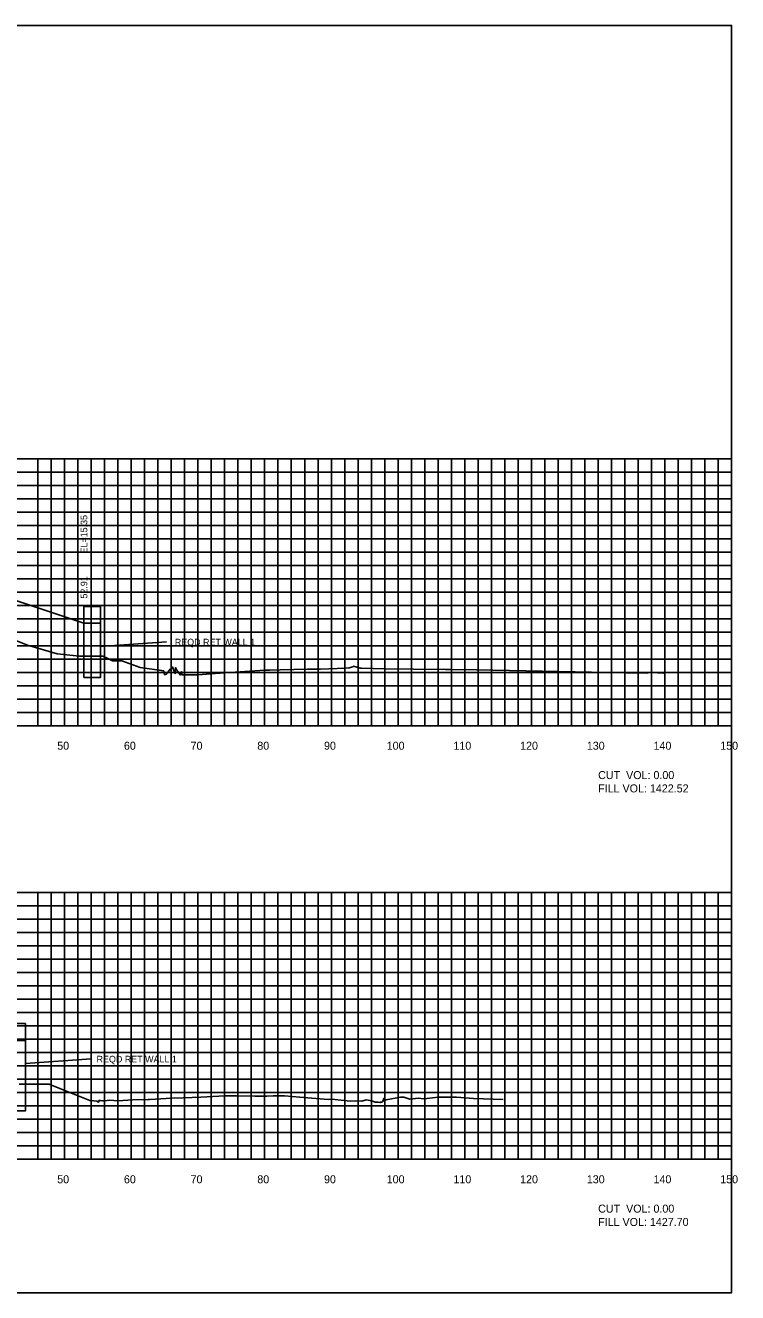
# Model space of a CAD drawing. Extents: x 1797652 to 1804145, y 245981 to 250269.
# Drawn here: x 1803355.1 to 1803461.9, y 250079.4 to 250269.4 of the extents above; entities that cross this region are included whole.
import ezdxf

# ---------------------------------------------------------------- set-up
doc = ezdxf.new("R2010")
doc.units = 0
for name, color, linetype in [('10', 7, 'Continuous'), ('3', 7, 'Continuous'), ('60', 7, 'Continuous'), ('ANNO-TXT', 7, 'Continuous'), ('CL-CNST', 7, 'Continuous'), ('Level 62', 7, 'Continuous'), ('M-ROADS', 7, 'Continuous')]:
    doc.layers.add(name, color=color, linetype=linetype)

msp = doc.modelspace()

# ---------------------------------------------------------------- linework, layer by layer
msp.add_line((1803363.91, 250179.78), (1803363.91, 250181.78))
msp.add_lwpolyline([(1803161, 250079.43), (1803461, 250079.43), (1803461, 250269.43), (1803161, 250269.43)], close=True)
at = {"layer": '3'}
for p, q in [((1803376.3, 250177.02), (1803366.41, 250176.31)), ((1803365.01, 250114.49), (1803355.12, 250113.78))]:
    msp.add_line(p, q, dxfattribs=at)
at = {"layer": '60'}
for p, q in [((1803461, 250164.43), (1803461, 250204.43)), ((1803461.06, 250204.43), (1803461, 250204.43)), ((1803461.06, 250194.43), (1803461, 250194.43)), ((1803461.06, 250184.43), (1803461, 250184.43)), ((1803461.06, 250174.43), (1803461, 250174.43)), ((1803161, 250164.43), (1803461, 250164.43)), ((1803361, 250164.37), (1803361, 250164.43)), ((1803371, 250164.37), (1803371, 250164.43)), ((1803381, 250164.37), (1803381, 250164.43)), ((1803391, 250164.37), (1803391, 250164.43)), ((1803401, 250164.37), (1803401, 250164.43)), ((1803411, 250164.37), (1803411, 250164.43)), ((1803421, 250164.37), (1803421, 250164.43)), ((1803431, 250164.37), (1803431, 250164.43)), ((1803441, 250164.37), (1803441, 250164.43)), ((1803451, 250164.37), (1803451, 250164.43)), ((1803461, 250164.37), (1803461, 250164.43)), ((1803461.06, 250164.43), (1803461, 250164.43)), ((1803461, 250099.43), (1803461, 250139.43)), ((1803461.06, 250139.43), (1803461, 250139.43)), ((1803461.06, 250129.43), (1803461, 250129.43)), ((1803461.06, 250119.43), (1803461, 250119.43)), ((1803461.06, 250109.43), (1803461, 250109.43)), ((1803161, 250099.43), (1803461, 250099.43)), ((1803361, 250099.37), (1803361, 250099.43)), ((1803371, 250099.37), (1803371, 250099.43)), ((1803381, 250099.37), (1803381, 250099.43)), ((1803391, 250099.37), (1803391, 250099.43)), ((1803401, 250099.37), (1803401, 250099.43)), ((1803411, 250099.37), (1803411, 250099.43)), ((1803421, 250099.37), (1803421, 250099.43)), ((1803431, 250099.37), (1803431, 250099.43)), ((1803441, 250099.37), (1803441, 250099.43)), ((1803451, 250099.37), (1803451, 250099.43)), ((1803461, 250099.37), (1803461, 250099.43)), ((1803461.06, 250099.43), (1803461, 250099.43))]:
    msp.add_line(p, q, dxfattribs=at)
at = {"layer": 'CL-CNST'}
msp.add_lwpolyline([(1803284.69, 250193.39), (1803286.5, 250193.32), (1803286.83, 250193.32), (1803287, 250192.82), (1803289, 250192.98), (1803295, 250193.11), (1803311, 250193.46), (1803319, 250193.14), (1803324.5, 250192.92), (1803363.91, 250179.78)], dxfattribs=at)
for points in [[(1803366.41, 250179.78), (1803363.91, 250179.78), (1803363.91, 250182.28), (1803366.41, 250182.28)], [(1803363.91, 250171.68), (1803366.41, 250171.68), (1803366.41, 250179.78), (1803363.91, 250179.78)], [(1803355.12, 250117.26), (1803352.62, 250117.26), (1803352.62, 250119.76), (1803355.12, 250119.76)], [(1803352.62, 250106.68), (1803355.12, 250106.68), (1803355.12, 250117.26), (1803352.62, 250117.26)]]:
    msp.add_lwpolyline(points, close=True, dxfattribs=at)
at = {"layer": 'Level 62'}
for p, q in [((1803161, 250204.43), (1803461, 250204.43)), ((1803357, 250164.43), (1803357, 250204.43)), ((1803359, 250164.43), (1803359, 250204.43)), ((1803361, 250164.43), (1803361, 250204.43)), ((1803363, 250164.43), (1803363, 250204.43)), ((1803365, 250164.43), (1803365, 250204.43)), ((1803367, 250164.43), (1803367, 250204.43)), ((1803369, 250164.43), (1803369, 250204.43)), ((1803371, 250164.43), (1803371, 250204.43)), ((1803373, 250164.43), (1803373, 250204.43)), ((1803375, 250164.43), (1803375, 250204.43)), ((1803377, 250164.43), (1803377, 250204.43)), ((1803379, 250164.43), (1803379, 250204.43)), ((1803381, 250164.43), (1803381, 250204.43)), ((1803383, 250164.43), (1803383, 250204.43)), ((1803385, 250164.43), (1803385, 250204.43)), ((1803387, 250164.43), (1803387, 250204.43)), ((1803389, 250164.43), (1803389, 250204.43)), ((1803391, 250164.43), (1803391, 250204.43)), ((1803393, 250164.43), (1803393, 250204.43)), ((1803395, 250164.43), (1803395, 250204.43)), ((1803397, 250164.43), (1803397, 250204.43)), ((1803399, 250164.43), (1803399, 250204.43)), ((1803401, 250164.43), (1803401, 250204.43)), ((1803403, 250164.43), (1803403, 250204.43)), ((1803405, 250164.43), (1803405, 250204.43)), ((1803407, 250164.43), (1803407, 250204.43)), ((1803409, 250164.43), (1803409, 250204.43)), ((1803411, 250164.43), (1803411, 250204.43)), ((1803413, 250164.43), (1803413, 250204.43)), ((1803415, 250164.43), (1803415, 250204.43)), ((1803417, 250164.43), (1803417, 250204.43)), ((1803419, 250164.43), (1803419, 250204.43)), ((1803421, 250164.43), (1803421, 250204.43)), ((1803423, 250164.43), (1803423, 250204.43)), ((1803425, 250164.43), (1803425, 250204.43)), ((1803427, 250164.43), (1803427, 250204.43)), ((1803429, 250164.43), (1803429, 250204.43)), ((1803431, 250164.43), (1803431, 250204.43)), ((1803433, 250164.43), (1803433, 250204.43)), ((1803435, 250164.43), (1803435, 250204.43)), ((1803437, 250164.43), (1803437, 250204.43)), ((1803439, 250164.43), (1803439, 250204.43)), ((1803441, 250164.43), (1803441, 250204.43)), ((1803443, 250164.43), (1803443, 250204.43)), ((1803445, 250164.43), (1803445, 250204.43)), ((1803447, 250164.43), (1803447, 250204.43)), ((1803449, 250164.43), (1803449, 250204.43)), ((1803451, 250164.43), (1803451, 250204.43)), ((1803453, 250164.43), (1803453, 250204.43)), ((1803455, 250164.43), (1803455, 250204.43)), ((1803457, 250164.43), (1803457, 250204.43)), ((1803459, 250164.43), (1803459, 250204.43)), ((1803461, 250164.43), (1803461, 250204.43)), ((1803161, 250202.43), (1803461, 250202.43)), ((1803161, 250200.43), (1803461, 250200.43)), ((1803161, 250198.43), (1803461, 250198.43)), ((1803161, 250196.43), (1803461, 250196.43)), ((1803161, 250194.43), (1803461, 250194.43)), ((1803161, 250192.43), (1803461, 250192.43)), ((1803161, 250190.43), (1803461, 250190.43)), ((1803161, 250188.43), (1803461, 250188.43)), ((1803161, 250186.43), (1803461, 250186.43)), ((1803161, 250184.43), (1803461, 250184.43)), ((1803161, 250182.43), (1803461, 250182.43)), ((1803161, 250180.43), (1803461, 250180.43)), ((1803161, 250178.43), (1803461, 250178.43)), ((1803161, 250176.43), (1803461, 250176.43)), ((1803161, 250174.43), (1803461, 250174.43)), ((1803161, 250172.43), (1803461, 250172.43)), ((1803161, 250170.43), (1803461, 250170.43)), ((1803161, 250168.43), (1803461, 250168.43)), ((1803161, 250166.43), (1803461, 250166.43)), ((1803161, 250164.43), (1803461, 250164.43)), ((1803161, 250139.43), (1803461, 250139.43)), ((1803357, 250099.43), (1803357, 250139.43)), ((1803359, 250099.43), (1803359, 250139.43)), ((1803361, 250099.43), (1803361, 250139.43)), ((1803363, 250099.43), (1803363, 250139.43)), ((1803365, 250099.43), (1803365, 250139.43)), ((1803367, 250099.43), (1803367, 250139.43)), ((1803369, 250099.43), (1803369, 250139.43)), ((1803371, 250099.43), (1803371, 250139.43)), ((1803373, 250099.43), (1803373, 250139.43)), ((1803375, 250099.43), (1803375, 250139.43)), ((1803377, 250099.43), (1803377, 250139.43)), ((1803379, 250099.43), (1803379, 250139.43)), ((1803381, 250099.43), (1803381, 250139.43)), ((1803383, 250099.43), (1803383, 250139.43)), ((1803385, 250099.43), (1803385, 250139.43)), ((1803387, 250099.43), (1803387, 250139.43)), ((1803389, 250099.43), (1803389, 250139.43)), ((1803391, 250099.43), (1803391, 250139.43)), ((1803393, 250099.43), (1803393, 250139.43)), ((1803395, 250099.43), (1803395, 250139.43)), ((1803397, 250099.43), (1803397, 250139.43)), ((1803399, 250099.43), (1803399, 250139.43)), ((1803401, 250099.43), (1803401, 250139.43)), ((1803403, 250099.43), (1803403, 250139.43)), ((1803405, 250099.43), (1803405, 250139.43)), ((1803407, 250099.43), (1803407, 250139.43)), ((1803409, 250099.43), (1803409, 250139.43)), ((1803411, 250099.43), (1803411, 250139.43)), ((1803413, 250099.43), (1803413, 250139.43)), ((1803415, 250099.43), (1803415, 250139.43)), ((1803417, 250099.43), (1803417, 250139.43)), ((1803419, 250099.43), (1803419, 250139.43)), ((1803421, 250099.43), (1803421, 250139.43)), ((1803423, 250099.43), (1803423, 250139.43)), ((1803425, 250099.43), (1803425, 250139.43)), ((1803427, 250099.43), (1803427, 250139.43)), ((1803429, 250099.43), (1803429, 250139.43)), ((1803431, 250099.43), (1803431, 250139.43)), ((1803433, 250099.43), (1803433, 250139.43)), ((1803435, 250099.43), (1803435, 250139.43)), ((1803437, 250099.43), (1803437, 250139.43)), ((1803439, 250099.43), (1803439, 250139.43)), ((1803441, 250099.43), (1803441, 250139.43)), ((1803443, 250099.43), (1803443, 250139.43)), ((1803445, 250099.43), (1803445, 250139.43)), ((1803447, 250099.43), (1803447, 250139.43)), ((1803449, 250099.43), (1803449, 250139.43)), ((1803451, 250099.43), (1803451, 250139.43)), ((1803453, 250099.43), (1803453, 250139.43)), ((1803455, 250099.43), (1803455, 250139.43)), ((1803457, 250099.43), (1803457, 250139.43)), ((1803459, 250099.43), (1803459, 250139.43)), ((1803461, 250099.43), (1803461, 250139.43)), ((1803161, 250137.43), (1803461, 250137.43)), ((1803161, 250135.43), (1803461, 250135.43)), ((1803161, 250133.43), (1803461, 250133.43)), ((1803161, 250131.43), (1803461, 250131.43)), ((1803161, 250129.43), (1803461, 250129.43)), ((1803161, 250127.43), (1803461, 250127.43)), ((1803161, 250125.43), (1803461, 250125.43)), ((1803161, 250123.43), (1803461, 250123.43)), ((1803161, 250121.43), (1803461, 250121.43)), ((1803161, 250119.43), (1803461, 250119.43)), ((1803161, 250117.43), (1803461, 250117.43)), ((1803161, 250115.43), (1803461, 250115.43)), ((1803161, 250113.43), (1803461, 250113.43)), ((1803161, 250111.43), (1803461, 250111.43)), ((1803161, 250109.43), (1803461, 250109.43)), ((1803161, 250107.43), (1803461, 250107.43)), ((1803161, 250105.43), (1803461, 250105.43)), ((1803161, 250103.43), (1803461, 250103.43)), ((1803161, 250101.43), (1803461, 250101.43)), ((1803161, 250099.43), (1803461, 250099.43))]:
    msp.add_line(p, q, dxfattribs=at)
at = {"layer": 'M-ROADS'}
for points in [[(1803352.2, 250177.82), (1803355.44, 250176.49), (1803359.88, 250175.2), (1803363.23, 250174.87), (1803363.32, 250174.87), (1803363.41, 250174.87), (1803366.73, 250174.88), (1803367.5, 250174.49), (1803368.21, 250174.17), (1803369.61, 250174.15), (1803372.35, 250173.16), (1803375.86, 250172.65), (1803376, 250172.06), (1803376.25, 250172.14), (1803376.89, 250172.95), (1803376.95, 250172.86), (1803377.12, 250173.23), (1803377.17, 250173.24), (1803377.24, 250173.13), (1803377.56, 250172.24), (1803377.56, 250172.23), (1803377.61, 250173.14), (1803377.7, 250173.03), (1803377.83, 250172.77), (1803378.21, 250172.21), (1803378.31, 250172.04), (1803378.39, 250172.09), (1803378.46, 250172.08), (1803378.53, 250172.54), (1803378.56, 250172.19), (1803378.65, 250172.05), (1803378.67, 250172.06), (1803379.13, 250172.06), (1803380.99, 250172.05), (1803383.58, 250172.26), (1803391.01, 250172.78), (1803391.77, 250172.78), (1803393.34, 250172.79), (1803397.4, 250172.91), (1803399.39, 250172.93), (1803403.1, 250173.08), (1803403.65, 250173.09), (1803404.24, 250173.24), (1803404.34, 250173.35), (1803404.69, 250173.27), (1803405.31, 250173.07), (1803405.36, 250173.06), (1803405.43, 250173.07), (1803405.52, 250173.08), (1803409.02, 250172.95), (1803417.6, 250172.88), (1803417.86, 250172.89), (1803418.11, 250172.88), (1803418.28, 250172.88), (1803418.32, 250172.87), (1803418.47, 250172.87), (1803418.85, 250172.85), (1803422.76, 250172.81), (1803444.96, 250172.36), (1803446.16, 250172.37), (1803448.41, 250172.33), (1803448.43, 250172.43), (1803448.71, 250172.42), (1803448.78, 250172.41), (1803448.91, 250172.39), (1803450.87, 250172.32), (1803450.93, 250172.28)], [(1803354.22, 250110.68), (1803355.94, 250110.68), (1803356.3, 250110.69), (1803358.56, 250110.69), (1803358.61, 250110.69), (1803358.67, 250110.69), (1803358.79, 250110.63), (1803364.77, 250108.24), (1803364.93, 250108.25), (1803365.83, 250108.16), (1803366.08, 250107.97), (1803366.13, 250108.08), (1803366.16, 250108.23), (1803366.4, 250108.22), (1803366.75, 250108.19), (1803366.83, 250108.19), (1803366.96, 250108.19), (1803367.03, 250108.19), (1803367.1, 250108.2), (1803367.7, 250108.3), (1803368.38, 250108.26), (1803369.01, 250108.21), (1803371.24, 250108.32), (1803373.55, 250108.39), (1803373.83, 250108.4), (1803377.05, 250108.61), (1803378.77, 250108.66), (1803381.42, 250108.74), (1803385.05, 250108.92), (1803386.79, 250108.92), (1803389.51, 250108.91), (1803391.32, 250108.91), (1803392.3, 250108.94), (1803393.62, 250108.92), (1803393.75, 250108.93), (1803393.8, 250108.95), (1803393.96, 250108.96), (1803396.25, 250108.75), (1803400.52, 250108.41), (1803401.07, 250108.42), (1803403.82, 250108.13), (1803404.6, 250108.18), (1803405.58, 250108.13), (1803406.23, 250108.32), (1803407.08, 250108.18), (1803407.57, 250108), (1803407.61, 250108), (1803407.95, 250108), (1803408, 250107.97), (1803408.26, 250107.96), (1803408.29, 250107.96), (1803408.34, 250107.93), (1803408.34, 250108), (1803408.61, 250108), (1803408.74, 250108.11), (1803408.85, 250108.56), (1803408.88, 250108.36), (1803408.94, 250108.33), (1803408.98, 250108.27), (1803409.03, 250108.34), (1803409.22, 250108.36), (1803411.38, 250108.75), (1803411.42, 250108.75), (1803411.43, 250108.75), (1803411.89, 250108.72), (1803412.79, 250108.42), (1803414.08, 250108.57), (1803414.8, 250108.5), (1803415.3, 250108.52), (1803416.99, 250108.73), (1803418.74, 250108.74), (1803419.78, 250108.75), (1803422.32, 250108.54), (1803426.74, 250108.39)]]:
    msp.add_lwpolyline(points, dxfattribs=at)

# ---------------------------------------------------------------- texts
at = {"layer": '10'}
for s, p in [('50', (1803359.9, 250160.83)), ('60', (1803369.9, 250160.83)), ('70', (1803379.9, 250160.83)), ('80', (1803389.9, 250160.83)), ('90', (1803399.9, 250160.83)), ('100', (1803409.3, 250160.83)), ('110', (1803419.3, 250160.83)), ('120', (1803429.3, 250160.83)), ('130', (1803439.3, 250160.83)), ('140', (1803449.3, 250160.83)), ('150', (1803459.3, 250160.83)), ('50', (1803359.9, 250095.83)), ('60', (1803369.9, 250095.83)), ('70', (1803379.9, 250095.83)), ('80', (1803389.9, 250095.83)), ('90', (1803399.9, 250095.83)), ('100', (1803409.3, 250095.83)), ('110', (1803419.3, 250095.83)), ('120', (1803429.3, 250095.83)), ('130', (1803439.3, 250095.83)), ('140', (1803449.3, 250095.83)), ('150', (1803459.3, 250095.83))]:
    msp.add_text(s, height=1.2, dxfattribs=at).set_placement(p)
at = {"layer": '3'}
for s, p in [('EL=15.35', (1803364.41, 250190.26)), ('52.91', (1803364.41, 250183.49))]:
    msp.add_text(s, height=1, rotation=90, dxfattribs=at).set_placement(p)
for p in [(1803377.53, 250176.46), (1803365.8, 250113.94)]:
    msp.add_text('REQD RET WALL 1', height=1, dxfattribs=at).set_placement(p)
at = {"layer": 'ANNO-TXT'}
for s, p in [('CUT  VOL: 0.00', (1803441, 250156.43)), ('FILL VOL: 1422.52', (1803441, 250154.43)), ('CUT  VOL: 0.00', (1803441, 250091.43)), ('FILL VOL: 1427.70', (1803441, 250089.43))]:
    msp.add_text(s, height=1.2, dxfattribs=at).set_placement(p)

doc.saveas('drawing.dxf')
